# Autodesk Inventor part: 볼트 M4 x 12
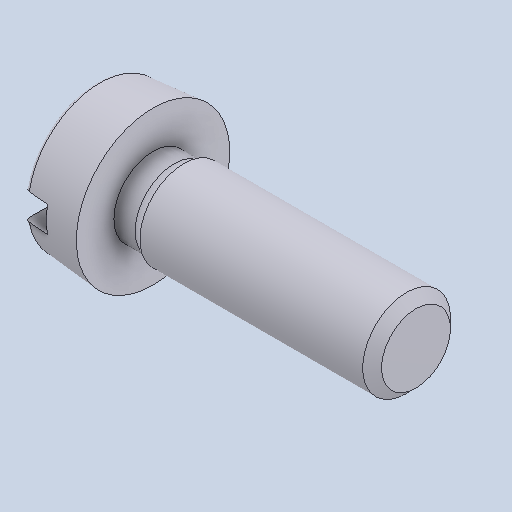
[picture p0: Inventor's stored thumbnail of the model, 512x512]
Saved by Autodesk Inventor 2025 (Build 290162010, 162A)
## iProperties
Created: 2024-07
Part Number: 볼트 M4 x 12
Material: 강철, 연강
Description: 6각머리 태핑 나사
Document SubType Name: Modeling
Designer: 학생
Density: 7.85 g/cm^3
Appearance: 기본값
Author: jhkim
Sending System: Autodesk Inventor 2025
Preprocessor: ST-DEVELOPER v20
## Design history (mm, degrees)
feature "Solid1"
node "솔리드1"
